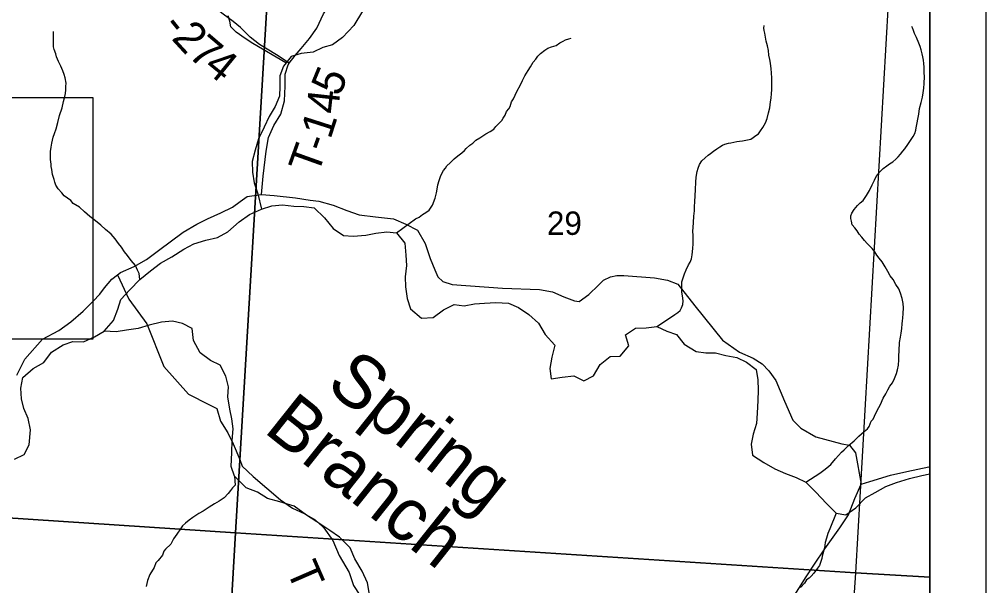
# Model space of a CAD drawing. Extents: x 0 to 34, y 0 to 22.
# Drawn here: x 7.274 to 9, y 15.171 to 16.183 of the extents above; entities that cross this region are included whole.
import ezdxf

# ---------------------------------------------------------------- set-up
doc = ezdxf.new("R2010")
doc.units = 0
for name, color, linetype in [('GM_X_Corporation', 7, 'Continuous'), ('GM_X_County_Road', 7, 'Continuous'), ('GM_X_Major_River', 7, 'Continuous'), ('GM_X_Minor_River', 7, 'Continuous'), ('GM_X_Minor_River_Text', 7, 'Continuous'), ('GM_X_Section_Text', 7, 'Continuous'), ('GM_X_Township_Road', 7, 'Continuous'), ('GM_X_Township_Road_Text', 7, 'Continuous'), ('SH_Data', 7, 'Continuous'), ('SH_Masking', 7, 'Continuous'), ('SH_Text', 7, 'Continuous')]:
    doc.layers.add(name, color=color, linetype=linetype)

msp = doc.modelspace()

# ---------------------------------------------------------------- linework, layer by layer
at = {"layer": 'GM_X_Corporation'}
for points in [[(3.3441, 14.1), (8.9, 14.1), (8.9, 20.9), (2.1, 20.9), (2.1, 16.1353), (2.1457, 16.065), (2.3447, 15.6926), (2.4297, 15.5215), (2.465, 15.4504), (2.4884, 15.4033), (2.5769, 15.2135), (2.7849, 14.8403), (2.8931, 14.6544), (3.0297, 14.4867), (3.1386, 14.3654), (3.228, 14.2415)], [(5.4627, 14.1), (8.9, 14.1), (8.9, 16.2015), (7.873, 16.2628), (7.7162, 16.2721), (7.5782, 16.28), (6.6249, 16.3344), (6.6163, 16.2457), (5.9321, 16.289), (5.8351, 16.2952), (5.6497, 16.3069), (5.6022, 16.3258), (5.5809, 15.9822), (5.4893, 14.5091), (5.4833, 14.4122), (5.4763, 14.3006)], [(6.6272, 16.3394), (7.7202, 16.2762), (7.66, 15.265), (6.5568, 15.3381), (6.621, 16.2504)], [(7.7202, 16.2762), (8.826, 16.2114), (8.7674, 15.1938), (7.66, 15.265)], [(8.9, 15.1859), (8.9, 16.207), (8.826, 16.2114), (8.7674, 15.1938)], [(6.5568, 15.3381), (7.66, 15.265), (7.6002, 14.2387), (6.4864, 14.308), (6.5491, 15.2271)], [(7.66, 15.265), (8.7674, 15.1938), (8.6977, 14.1705), (7.6002, 14.2387)], [(8.9, 14.1574), (8.9, 15.1859), (8.7674, 15.1938), (8.6977, 14.1705)]]:
    msp.add_lwpolyline(points, close=True, dxfattribs=at)
at = {"layer": 'GM_X_County_Road'}
for points in [[(7.269, 15.547), (7.2834, 15.5759), (7.315, 15.6112), (7.3442, 15.6267), (7.3659, 15.6423), (7.3876, 15.6613), (7.4058, 15.6791), (7.4172, 15.6916), (7.4256, 15.703), (7.4389, 15.7186), (7.4491, 15.7265), (7.4545, 15.7307), (7.4788, 15.741), (7.5008, 15.7539), (7.5221, 15.7702), (7.5666, 15.8028), (7.5905, 15.8172), (7.6099, 15.8267), (7.6338, 15.8374), (7.6547, 15.8472), (7.668, 15.8575), (7.6806, 15.8662), (7.706, 15.87), (7.7288, 15.8681), (7.7672, 15.8643), (7.793, 15.8597), (7.8089, 15.8582), (7.8344, 15.851), (7.8587, 15.8415), (7.8807, 15.8339), (7.9099, 15.83), (7.9422, 15.8266), (7.9643, 15.8171), (7.9848, 15.8065), (7.9984, 15.7826), (8.0075, 15.7556), (8.0158, 15.7355), (8.0211, 15.7229), (8.0302, 15.7142), (8.047, 15.7093), (8.1366, 15.7024), (8.203, 15.7001), (8.2262, 15.6959), (8.2463, 15.6868), (8.2657, 15.6799), (8.2737, 15.6788), (8.2908, 15.691), (8.3083, 15.7077), (8.317, 15.7168), (8.3295, 15.7228), (8.3413, 15.7255), (8.3535, 15.7251), (8.4082, 15.7213), (8.4313, 15.7168), (8.4499, 15.7095), (8.4803, 15.6708), (8.5296, 15.6093), (8.5604, 15.588), (8.5847, 15.5774), (8.601, 15.5675), (8.6124, 15.5546), (8.6253, 15.5375), (8.6404, 15.5003), (8.6556, 15.4668), (8.6696, 15.4524), (8.6966, 15.4365), (8.7429, 15.4243), (8.7566, 15.4216), (8.7672, 15.408), (8.7778, 15.3521)], [(8.653, 15.1445), (8.6793, 15.1866), (8.6945, 15.209), (8.7127, 15.2363), (8.7397, 15.2739), (8.755, 15.2975), (8.7664, 15.3267), (8.7778, 15.3521), (8.793, 15.3571), (8.8302, 15.3685), (8.8591, 15.3745), (8.8986, 15.3829), (8.9, 15.383)]]:
    msp.add_lwpolyline(points, dxfattribs=at)
at = {"layer": 'GM_X_Major_River'}
for points in [[(7.2648, 15.397), (7.2823, 15.4053), (7.2914, 15.4227), (7.2938, 15.4492), (7.2893, 15.4697), (7.2818, 15.4872), (7.2773, 15.5046), (7.2766, 15.5236), (7.2797, 15.5426), (7.2986, 15.5592), (7.3176, 15.5697), (7.3313, 15.5879), (7.3518, 15.6015), (7.3692, 15.6075), (7.3881, 15.6067), (7.4078, 15.6157), (7.4253, 15.6256), (7.442, 15.6445), (7.4496, 15.6649), (7.455, 15.6823), (7.4709, 15.6997), (7.4891, 15.7179), (7.5081, 15.7338), (7.5256, 15.7474), (7.546, 15.7587), (7.5673, 15.7723), (7.5855, 15.7821), (7.6067, 15.7881), (7.6279, 15.7933), (7.6461, 15.8031), (7.6666, 15.8213), (7.6848, 15.8341), (7.706, 15.8439), (7.725, 15.8499), (7.7439, 15.8514), (7.7643, 15.8491), (7.7817, 15.8483), (7.8006, 15.8459), (7.8188, 15.8284), (7.8346, 15.8094), (7.8527, 15.7965), (7.8701, 15.7957), (7.8928, 15.7971), (7.9103, 15.8009), (7.93, 15.8031), (7.9474, 15.8015), (7.9624, 15.7833), (7.9639, 15.7613), (7.9653, 15.7431), (7.963, 15.7226), (7.9637, 15.7052), (7.9667, 15.6839), (7.9727, 15.6657), (7.9923, 15.649), (8.0127, 15.6504), (8.0317, 15.664), (8.0507, 15.6731), (8.0681, 15.6708), (8.087, 15.6745), (8.1044, 15.676), (8.1249, 15.6767), (8.1476, 15.6758), (8.1657, 15.6682), (8.1838, 15.6553), (8.2012, 15.64), (8.2132, 15.6195), (8.2306, 15.6005), (8.2252, 15.5793), (8.2214, 15.5588), (8.2236, 15.5406), (8.2433, 15.5436), (8.2645, 15.5458), (8.2819, 15.5367), (8.2993, 15.5457), (8.3115, 15.5662), (8.3289, 15.5805), (8.3471, 15.5812), (8.3623, 15.5994), (8.3563, 15.6191), (8.3745, 15.6312), (8.3934, 15.6319), (8.4124, 15.6342)], [(8.4124, 15.6342), (8.4305, 15.6258), (8.4479, 15.6197), (8.4615, 15.6022), (8.4826, 15.5892), (8.5, 15.5869), (8.5174, 15.5869), (8.5356, 15.5823), (8.5553, 15.5784), (8.5726, 15.57), (8.59, 15.5571), (8.593, 15.5389), (8.5937, 15.5199), (8.5929, 15.5017), (8.592, 15.479), (8.5905, 15.4608), (8.5844, 15.4418), (8.5813, 15.4236), (8.5835, 15.4039), (8.6039, 15.391), (8.6235, 15.3795), (8.6424, 15.3711), (8.6613, 15.3643), (8.6787, 15.3559), (8.6968, 15.3376), (8.7157, 15.3178), (8.733, 15.3004), (8.7504, 15.2973), (8.7679, 15.3101), (8.7854, 15.3275), (8.8028, 15.3373), (8.8218, 15.3479), (8.8407, 15.3554), (8.8642, 15.3622), (8.8862, 15.3675), (8.9, 15.3709)]]:
    msp.add_lwpolyline(points, dxfattribs=at)
at = {"layer": 'GM_X_Minor_River'}
for points in [[(7.8865, 16.1976), (7.8713, 16.1719), (7.8508, 16.1507), (7.8333, 16.1379), (7.8159, 16.1326), (7.7985, 16.1243), (7.7773, 16.1221), (7.7591, 16.1168), (7.7454, 16.0994), (7.7393, 16.082), (7.7393, 16.063), (7.7384, 16.0456), (7.7308, 16.0274), (7.7202, 16.0092), (7.711, 15.9903), (7.7011, 15.9698), (7.695, 15.9494), (7.6896, 15.9289), (7.6903, 15.91), (7.6933, 15.891), (7.7, 15.8712), (7.706, 15.8439)], [(7.75, 16.1052), (7.6911, 16.14), (7.6771, 16.1491), (7.6608, 16.1604), (7.6514, 16.1699), (7.6495, 16.1797), (7.6468, 16.1892)], [(7.4891, 15.7179), (7.4875, 15.7288), (7.4846, 15.7349), (7.4813, 15.7429), (7.4735, 15.7522), (7.4668, 15.761), (7.4617, 15.7676), (7.4561, 15.776), (7.4506, 15.7826), (7.4446, 15.7906), (7.4376, 15.7991), (7.4279, 15.8076), (7.4193, 15.815), (7.41, 15.8228), (7.3999, 15.8309), (7.3898, 15.839), (7.3809, 15.8472), (7.37, 15.8538), (7.3659, 15.8592), (7.3539, 15.8674), (7.3495, 15.8728), (7.3428, 15.8801), (7.3388, 15.887), (7.337, 15.892), (7.3359, 15.8969), (7.333, 15.9057), (7.3317, 15.9145), (7.3306, 15.9202), (7.3303, 15.9244), (7.3293, 15.9327), (7.3291, 15.9403), (7.3296, 15.9472), (7.3305, 15.9544), (7.3317, 15.9616), (7.333, 15.9672), (7.3342, 15.9725), (7.3366, 15.9793), (7.3394, 15.9876), (7.3426, 15.9986), (7.3455, 16.0115), (7.3503, 16.0251), (7.3528, 16.0364), (7.3552, 16.0455), (7.356, 16.0508), (7.3565, 16.0569), (7.357, 16.0629), (7.3571, 16.069), (7.3554, 16.0785), (7.354, 16.0846), (7.3514, 16.0911), (7.3478, 16.0992), (7.3434, 16.1076), (7.3416, 16.1118), (7.3401, 16.116), (7.3387, 16.1217), (7.3362, 16.1294), (7.3348, 16.1339), (7.3349, 16.1613)], [(8.4124, 15.6342), (8.4403, 15.6527), (8.4449, 15.6557), (8.4499, 15.659), (8.4541, 15.6627), (8.4564, 15.6673), (8.4592, 15.6733), (8.4593, 15.6801), (8.4583, 15.6889), (8.4573, 15.6953), (8.4571, 15.7022), (8.4573, 15.7136), (8.4593, 15.7211), (8.4621, 15.7279), (8.4652, 15.7351), (8.4692, 15.7441), (8.4723, 15.749), (8.4743, 15.7551), (8.4755, 15.7623), (8.4769, 15.7733), (8.4774, 15.782), (8.4775, 15.7888), (8.4773, 15.7968), (8.477, 15.8044), (8.4775, 15.8109), (8.4781, 15.82), (8.4786, 15.831), (8.4796, 15.8408), (8.4801, 15.848), (8.4806, 15.8575), (8.4808, 15.8674), (8.4814, 15.8792), (8.482, 15.8921), (8.4829, 15.9008), (8.4846, 15.911), (8.4862, 15.9171), (8.4886, 15.9239), (8.4929, 15.9302), (8.4987, 15.9358), (8.5041, 15.9403), (8.5083, 15.9433), (8.514, 15.9477), (8.5198, 15.9518), (8.5248, 15.9555), (8.5297, 15.9585), (8.5343, 15.9603), (8.5404, 15.9621), (8.5446, 15.9624), (8.5499, 15.9635), (8.5556, 15.9645), (8.5602, 15.9652), (8.5655, 15.9659), (8.5746, 15.968), (8.5803, 15.969), (8.5849, 15.972), (8.5895, 15.9757), (8.5941, 15.9787), (8.5976, 15.9836), (8.6019, 15.9899), (8.6066, 15.9982), (8.6094, 16.0062), (8.6122, 16.016), (8.6142, 16.0247), (8.6156, 16.0357), (8.6165, 16.0425), (8.6173, 16.0505), (8.6178, 16.0569), (8.6182, 16.0782), (8.6176, 16.0873), (8.6166, 16.0945), (8.6157, 16.1048), (8.6146, 16.1113), (8.6125, 16.1193), (8.6119, 16.1273), (8.6101, 16.1357), (8.608, 16.1444), (8.6052, 16.1582), (8.6042, 16.1631), (8.6039, 16.1677), (8.604, 16.1719)], [(8.8906, 16.0808), (8.8903, 16.0877), (8.8901, 16.0979), (8.8895, 16.104), (8.8892, 16.1101), (8.8878, 16.1162), (8.8868, 16.1215), (8.885, 16.1288), (8.8828, 16.1345), (8.8803, 16.1406), (8.8763, 16.151), (8.873, 16.1579), (8.8708, 16.1632), (8.869, 16.1678), (8.8679, 16.1705)], [(7.9474, 15.8015), (7.9816, 15.8268), (7.9877, 15.8297), (7.9942, 15.8342), (7.9996, 15.8379), (8.0058, 15.8423), (8.012, 15.851), (8.0163, 15.8634), (8.0188, 15.8729), (8.02, 15.8797), (8.0213, 15.8873), (8.0237, 15.8948), (8.0265, 15.9039), (8.0312, 15.9129), (8.0351, 15.917), (8.0374, 15.9212), (8.0436, 15.9268), (8.0502, 15.9339), (8.0571, 15.9394), (8.0644, 15.9446), (8.069, 15.9484), (8.0717, 15.9525), (8.0786, 15.9585), (8.0836, 15.9618), (8.0894, 15.967), (8.0963, 15.9715), (8.107, 15.9785), (8.115, 15.9825), (8.1212, 15.987), (8.125, 15.9915), (8.1289, 15.9956), (8.1358, 16.0023), (8.1378, 16.0065), (8.1417, 16.0117), (8.1441, 16.0185), (8.1479, 16.0234), (8.1503, 16.0275), (8.1531, 16.0355), (8.1566, 16.0411), (8.1597, 16.0475), (8.1625, 16.0543), (8.1688, 16.0663), (8.1723, 16.0739), (8.1766, 16.0822), (8.1825, 16.0916), (8.1871, 16.0983), (8.1918, 16.1066), (8.1965, 16.1118), (8.2, 16.1175), (8.205, 16.1219), (8.2127, 16.1283), (8.218, 16.1316), (8.2241, 16.1338), (8.2287, 16.1352), (8.2329, 16.1367), (8.2394, 16.1411), (8.2451, 16.1441), (8.2494, 16.1463), (8.2554, 16.1484), (8.2596, 16.1495)], [(8.6787, 15.3559), (8.7035, 15.3718), (8.7108, 15.377), (8.7162, 15.3811), (8.7235, 15.3874), (8.7316, 15.3976), (8.7424, 15.4095), (8.747, 15.4136), (8.7551, 15.4211), (8.7651, 15.4297), (8.7736, 15.4379), (8.7828, 15.4465), (8.7886, 15.4509), (8.7917, 15.455), (8.7957, 15.4645), (8.7991, 15.4686), (8.8035, 15.4788), (8.809, 15.4893), (8.8121, 15.4946), (8.8168, 15.5059), (8.8219, 15.5134), (8.8254, 15.5209), (8.829, 15.5273), (8.8336, 15.5333), (8.8372, 15.5413), (8.8404, 15.5499), (8.8427, 15.5564), (8.844, 15.5647), (8.8446, 15.5742), (8.8451, 15.5814), (8.8452, 15.5905), (8.8463, 15.6057), (8.8479, 15.6148), (8.8488, 15.622), (8.8497, 15.6265), (8.8501, 15.6307), (8.8506, 15.6386), (8.8515, 15.6439), (8.8519, 15.6489), (8.8528, 15.6572), (8.8534, 15.6671), (8.8524, 15.6754), (8.8507, 15.6838), (8.8478, 15.6938), (8.8449, 15.7014), (8.8397, 15.7091), (8.8346, 15.7179), (8.8294, 15.7248), (8.8254, 15.7321), (8.8206, 15.7405), (8.8151, 15.7498), (8.8099, 15.7559), (8.8058, 15.7617), (8.8018, 15.7678), (8.7973, 15.7732), (8.7925, 15.7782), (8.788, 15.7825), (8.7836, 15.7879), (8.7787, 15.794), (8.7739, 15.7991), (8.7702, 15.8048), (8.7662, 15.8106), (8.7617, 15.816), (8.7603, 15.8221), (8.7593, 15.8274), (8.7593, 15.8316), (8.7609, 15.8365), (8.7648, 15.8433), (8.771, 15.8504), (8.776, 15.8549), (8.7814, 15.8593), (8.7872, 15.868), (8.7923, 15.877), (8.7974, 15.8872), (8.8014, 15.8954), (8.8057, 15.9045), (8.8103, 15.9101), (8.8169, 15.9168), (8.8234, 15.9213), (8.828, 15.9246), (8.8341, 15.9287), (8.8395, 15.9332), (8.8434, 15.9373), (8.848, 15.9421), (8.8523, 15.9474), (8.8558, 15.9515), (8.8608, 15.9594), (8.8702, 15.9737), (8.8733, 15.9789), (8.8753, 15.985), (8.8761, 15.9892), (8.8774, 15.9979), (8.8787, 16.0047), (8.8803, 16.0134), (8.882, 16.0236), (8.8845, 16.0346), (8.8869, 16.044), (8.8882, 16.0516), (8.8895, 16.0603), (8.8904, 16.0687), (8.8906, 16.0808)], [(7.8992, 15.1548), (7.8954, 15.176), (7.8864, 15.1965), (7.8729, 15.2185), (7.8646, 15.2383), (7.8457, 15.2573), (7.8284, 15.2695), (7.8049, 15.2847), (7.7868, 15.2969), (7.7649, 15.3129), (7.7392, 15.3205), (7.7173, 15.3267), (7.6991, 15.3381), (7.6787, 15.3457), (7.6583, 15.3663), (7.6523, 15.3837), (7.6532, 15.4088), (7.654, 15.43), (7.6556, 15.4512), (7.6534, 15.4687), (7.6496, 15.4861), (7.6459, 15.5081), (7.6475, 15.5263), (7.6423, 15.5453), (7.6325, 15.565), (7.6151, 15.5734), (7.597, 15.5871), (7.5849, 15.6092), (7.5827, 15.6304), (7.5653, 15.6396), (7.5472, 15.6434), (7.5275, 15.6419), (7.5055, 15.6367), (7.4858, 15.6307), (7.4654, 15.6277), (7.4465, 15.6247), (7.4253, 15.6256)], [(7.6583, 15.3663), (7.6592, 15.3503), (7.6546, 15.3454), (7.6507, 15.3406), (7.6465, 15.3357), (7.6395, 15.3274), (7.6307, 15.3219), (7.6223, 15.3167), (7.6127, 15.3108), (7.602, 15.3038), (7.5943, 15.2994), (7.5836, 15.2927), (7.5771, 15.2879), (7.5705, 15.2823), (7.5651, 15.2774), (7.5613, 15.2722), (7.555, 15.2628), (7.5492, 15.2542), (7.5441, 15.2448), (7.5349, 15.2362), (7.5321, 15.2321), (7.5294, 15.2253), (7.5216, 15.2155), (7.5174, 15.2114), (7.5146, 15.2031), (7.5068, 15.1907), (7.5028, 15.1801), (7.5004, 15.1692)], [(8.733, 15.3004), (8.7218, 15.2724), (8.7183, 15.2641), (8.7155, 15.2558), (8.7134, 15.2479), (8.7121, 15.238), (8.7081, 15.2236), (8.7076, 15.2191), (8.7029, 15.2066), (8.6994, 15.2021), (8.6932, 15.1931), (8.6881, 15.1879), (8.6847, 15.1838), (8.6801, 15.1808), (8.6766, 15.1752), (8.6692, 15.1673)]]:
    msp.add_lwpolyline(points, dxfattribs=at)
at = {"layer": 'GM_X_Township_Road'}
for points in [[(7.7559, 16.1046), (7.7328, 16.1199), (7.7028, 16.1385), (7.6858, 16.1514), (7.6687, 16.1685), (7.6558, 16.1795), (7.6379, 16.1924), (7.6266, 16.2015), (7.6137, 16.2171), (7.603, 16.2388), (7.5913, 16.2642), (7.5784, 16.2795), (7.5746, 16.284), (7.5611, 16.2941), (7.5484, 16.3037), (7.5441, 16.3069)], [(7.706, 15.87), (7.7091, 15.9026), (7.7148, 15.9478), (7.719, 15.9721), (7.7285, 15.9934), (7.7411, 16.0135), (7.7476, 16.0374), (7.7483, 16.064), (7.7484, 16.0849), (7.7537, 16.1016), (7.7559, 16.1046), (7.7663, 16.1187), (7.7773, 16.1309), (7.7921, 16.1491), (7.805, 16.1677), (7.8168, 16.1931), (7.8281, 16.2111)], [(7.4491, 15.7265), (7.4691, 15.6826), (7.5015, 15.6388), (7.532, 15.5626), (7.5758, 15.5131), (7.612, 15.4947)], [(7.612, 15.4947), (7.6267, 15.4872), (7.6328, 15.4648), (7.646, 15.444), (7.6559, 15.4242), (7.6676, 15.3965), (7.6718, 15.3843), (7.6915, 15.3661), (7.7405, 15.3239), (7.7614, 15.3095), (7.7826, 15.2996), (7.8024, 15.2882), (7.8157, 15.2758)], [(7.8157, 15.2758), (7.8179, 15.2738), (7.8335, 15.2514), (7.8452, 15.2244), (7.8627, 15.1944), (7.8706, 15.1712), (7.882, 15.1534)]]:
    msp.add_lwpolyline(points, dxfattribs=at)
at = {"layer": 'SH_Data'}
for p, q in [((9, 21), (9, 14)), ((8.9, 20.9), (8.9, 14.1))]:
    msp.add_line(p, q, dxfattribs=at)
at = {"layer": 'SH_Masking'}
msp.add_lwpolyline([(5.9375, 16.0436), (7.4049, 16.0436), (7.4049, 15.6115), (5.9375, 15.6115)], close=True, dxfattribs=at)
at = {"layer": 'SH_Text'}
msp.add_lwpolyline([(5.9375, 16.0436), (7.4049, 16.0436), (7.4049, 15.6115), (5.9375, 15.6115)], close=True, dxfattribs=at)

# ---------------------------------------------------------------- texts
at = {"layer": 'GM_X_Minor_River_Text'}
for s, rotation, p in [('Spring', 321.4993, (7.8187, 15.5249)), ('Branch', 321.4987, (7.7081, 15.4466))]:
    msp.add_text(s, height=0.09468, rotation=rotation, dxfattribs=at).set_placement(p)
at = {"layer": 'GM_X_Section_Text'}
msp.add_text('29', height=0.04186, rotation=0, dxfattribs=at).set_placement((8.2163, 15.7978))
at = {"layer": 'GM_X_Township_Road_Text'}
for s, rotation, p in [('-', 308.7263, (7.5267, 16.1699)), ('2', 312.5788, (7.544, 16.1485)), ('7', 319.5388, (7.5731, 16.1175)), ('4', 320.7602, (7.6008, 16.094)), ('5', 67.6091, (7.8455, 16.0434)), ('4', 83.7529, (7.8427, 16.0127)), ('1', 72.1992, (7.8294, 15.9672)), ('-', 70.5632, (7.8211, 15.9435)), ('T', 70.2944, (7.8067, 15.9032)), ('T', 293.4812, (7.7498, 15.1994))]:
    msp.add_text(s, height=0.0568, rotation=rotation, dxfattribs=at).set_placement(p)

doc.saveas('drawing.dxf')
